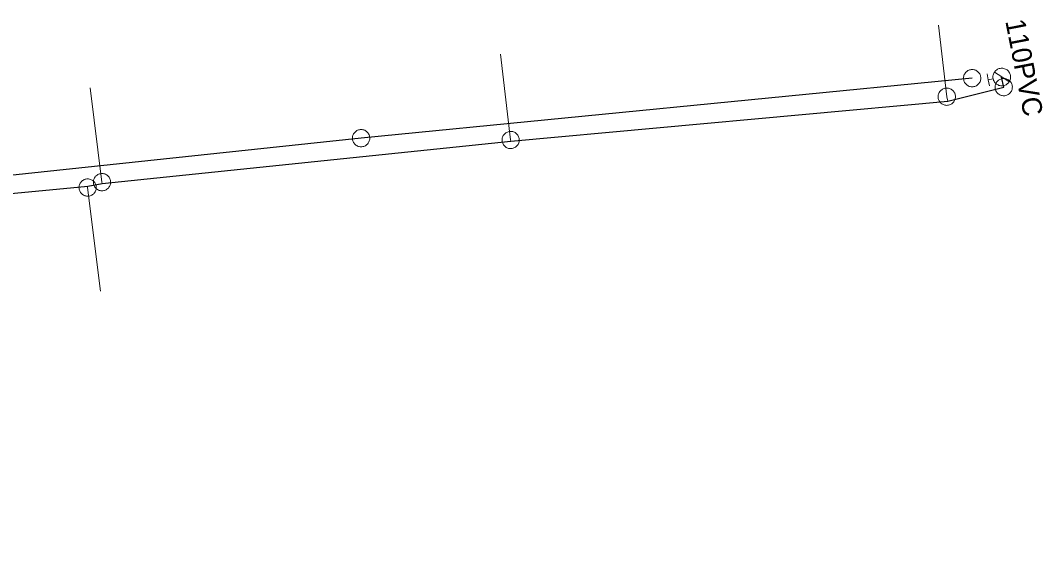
# Model space of a CAD drawing. Extents: x -741806 to -738704, y -1059275 to -1055387.
# Drawn here: x -740331.3 to -740279.6, y -1057572.5 to -1057546.2 of the extents above; entities that cross this region are included whole.
import ezdxf

# ---------------------------------------------------------------- set-up
doc = ezdxf.new("R2010")
doc.units = 0
doc.header["$LTSCALE"] = 0.4
for name, color, linetype, lineweight in [('2', 7, 'Continuous', 25), ('21', 7, 'Continuous', 13), ('3', 7, 'Continuous', 13), ('50', 7, 'Continuous', 13), ('51', 7, 'Continuous', 13), ('52', 7, 'Continuous', 25)]:
    doc.layers.add(name, color=color, linetype=linetype, lineweight=lineweight)
doc.layers.add('53', color=7, linetype='Continuous')

msp = doc.modelspace()

# ---------------------------------------------------------------- linework, layer by layer
at = {"layer": '2'}
msp.add_lwpolyline([(-740283.166, -1057549.12), (-740314.092, -1057552.159), (-740363.478, -1057557.404), (-740409.581, -1057562.408), (-740464.129, -1057568.401), (-740509.967, -1057572.304)], dxfattribs=at)
at = {"layer": '21'}
for points in [[(-740284.403, -1057550.291), (-740284.452, -1057550.058), (-740284.875, -1057546.442)], [(-740306.52, -1057552.313), (-740306.524, -1057552.25), (-740307.032, -1057547.902)], [(-740327.193, -1057554.446), (-740327.206, -1057554.386), (-740327.807, -1057549.607)], [(-740327.93, -1057554.585), (-740327.931, -1057554.659), (-740327.281, -1057559.914)]]:
    msp.add_lwpolyline(points, dxfattribs=at)
at = {"layer": '3'}
for points in [[(-740283.601, -1057549.162), (-740283.594, -1057549.206), (-740283.583, -1057549.25), (-740283.566, -1057549.294), (-740283.546, -1057549.334), (-740283.521, -1057549.373), (-740283.493, -1057549.409), (-740283.46, -1057549.441), (-740283.425, -1057549.471), (-740283.387, -1057549.495), (-740283.347, -1057549.517), (-740283.304, -1057549.533), (-740283.259, -1057549.546), (-740283.214, -1057549.553), (-740283.169, -1057549.556), (-740283.123, -1057549.554), (-740283.077, -1057549.547), (-740283.033, -1057549.535), (-740282.991, -1057549.52), (-740282.949, -1057549.499), (-740282.911, -1057549.474), (-740282.875, -1057549.445), (-740282.843, -1057549.414), (-740282.814, -1057549.378), (-740282.788, -1057549.34), (-740282.767, -1057549.299), (-740282.751, -1057549.256), (-740282.738, -1057549.213), (-740282.731, -1057549.167), (-740282.728, -1057549.121), (-740282.731, -1057549.075), (-740282.737, -1057549.031), (-740282.749, -1057548.987), (-740282.765, -1057548.943), (-740282.786, -1057548.902), (-740282.81, -1057548.864), (-740282.838, -1057548.828), (-740282.871, -1057548.796), (-740282.907, -1057548.766), (-740282.944, -1057548.742), (-740282.985, -1057548.72), (-740283.028, -1057548.704), (-740283.072, -1057548.691), (-740283.117, -1057548.683), (-740283.162, -1057548.681), (-740283.208, -1057548.683), (-740283.254, -1057548.69), (-740283.298, -1057548.701), (-740283.341, -1057548.717), (-740283.382, -1057548.738), (-740283.421, -1057548.763), (-740283.456, -1057548.792), (-740283.489, -1057548.823), (-740283.518, -1057548.859), (-740283.543, -1057548.897), (-740283.564, -1057548.938), (-740283.581, -1057548.981), (-740283.593, -1057549.024), (-740283.6, -1057549.07), (-740283.603, -1057549.116), (-740283.602, -1057549.161)], [(-740314.527, -1057552.201), (-740314.52, -1057552.245), (-740314.509, -1057552.289), (-740314.492, -1057552.333), (-740314.472, -1057552.373), (-740314.447, -1057552.412), (-740314.419, -1057552.448), (-740314.386, -1057552.48), (-740314.351, -1057552.51), (-740314.313, -1057552.534), (-740314.273, -1057552.556), (-740314.23, -1057552.572), (-740314.185, -1057552.585), (-740314.14, -1057552.592), (-740314.095, -1057552.595), (-740314.049, -1057552.593), (-740314.003, -1057552.586), (-740313.959, -1057552.574), (-740313.917, -1057552.559), (-740313.875, -1057552.538), (-740313.837, -1057552.513), (-740313.801, -1057552.484), (-740313.769, -1057552.453), (-740313.74, -1057552.417), (-740313.714, -1057552.379), (-740313.693, -1057552.338), (-740313.677, -1057552.295), (-740313.664, -1057552.252), (-740313.657, -1057552.206), (-740313.654, -1057552.16), (-740313.657, -1057552.114), (-740313.663, -1057552.07), (-740313.675, -1057552.026), (-740313.691, -1057551.982), (-740313.712, -1057551.941), (-740313.736, -1057551.903), (-740313.764, -1057551.867), (-740313.797, -1057551.835), (-740313.833, -1057551.805), (-740313.87, -1057551.781), (-740313.911, -1057551.759), (-740313.954, -1057551.743), (-740313.998, -1057551.73), (-740314.043, -1057551.722), (-740314.088, -1057551.72), (-740314.134, -1057551.722), (-740314.18, -1057551.729), (-740314.224, -1057551.74), (-740314.267, -1057551.756), (-740314.308, -1057551.777), (-740314.347, -1057551.802), (-740314.382, -1057551.831), (-740314.415, -1057551.862), (-740314.444, -1057551.898), (-740314.469, -1057551.936), (-740314.49, -1057551.977), (-740314.507, -1057552.02), (-740314.519, -1057552.063), (-740314.526, -1057552.109), (-740314.529, -1057552.155), (-740314.528, -1057552.2)]]:
    msp.add_lwpolyline(points, dxfattribs=at)
at = {"layer": '50'}
for p, q in [((-740282.413, -1057548.897), (-740282.352, -1057549.198)), ((-740281.668, -1057549.059), (-740282.036, -1057548.811)), ((-740282.106, -1057549.148), (-740282.352, -1057549.198)), ((-740282.291, -1057549.499), (-740282.352, -1057549.198)), ((-740281.668, -1057549.059), (-740281.295, -1057549.307))]:
    msp.add_line(p, q, dxfattribs=at)
msp.add_lwpolyline([(-740281.752, -1057548.623), (-740281.799, -1057548.635), (-740281.843, -1057548.649), (-740281.886, -1057548.671), (-740281.925, -1057548.696), (-740281.96, -1057548.723), (-740281.995, -1057548.757), (-740282.024, -1057548.793), (-740282.051, -1057548.832), (-740282.074, -1057548.872), (-740282.09, -1057548.916), (-740282.103, -1057548.961), (-740282.113, -1057549.007), (-740282.114, -1057549.054), (-740282.113, -1057549.1), (-740282.106, -1057549.146), (-740282.094, -1057549.19), (-740282.081, -1057549.234), (-740282.059, -1057549.276), (-740282.033, -1057549.316), (-740282.004, -1057549.354), (-740281.972, -1057549.386), (-740281.937, -1057549.417), (-740281.898, -1057549.443), (-740281.858, -1057549.464), (-740281.813, -1057549.483), (-740281.769, -1057549.496), (-740281.723, -1057549.503), (-740281.675, -1057549.508), (-740281.629, -1057549.504), (-740281.583, -1057549.501), (-740281.537, -1057549.488), (-740281.493, -1057549.471), (-740281.453, -1057549.452), (-740281.411, -1057549.427), (-740281.375, -1057549.397), (-740281.341, -1057549.366), (-740281.313, -1057549.33), (-740281.285, -1057549.291), (-740281.263, -1057549.248), (-740281.247, -1057549.206), (-740281.234, -1057549.16), (-740281.226, -1057549.114), (-740281.221, -1057549.07), (-740281.223, -1057549.02), (-740281.229, -1057548.974), (-740281.241, -1057548.93), (-740281.258, -1057548.886), (-740281.278, -1057548.843), (-740281.302, -1057548.804), (-740281.332, -1057548.766), (-740281.363, -1057548.734), (-740281.4, -1057548.703), (-740281.438, -1057548.678), (-740281.478, -1057548.655), (-740281.523, -1057548.64), (-740281.567, -1057548.624), (-740281.613, -1057548.616), (-740281.66, -1057548.615), (-740281.706, -1057548.616)], close=True, dxfattribs=at)
at = {"layer": '51'}
for points in [[(-740281.146, -1057549.463), (-740281.159, -1057549.42), (-740281.177, -1057549.378), (-740281.2, -1057549.338), (-740281.225, -1057549.301), (-740281.256, -1057549.266), (-740281.29, -1057549.235), (-740281.326, -1057549.208), (-740281.366, -1057549.184), (-740281.407, -1057549.166), (-740281.45, -1057549.151), (-740281.495, -1057549.14), (-740281.541, -1057549.135), (-740281.587, -1057549.134), (-740281.632, -1057549.138), (-740281.677, -1057549.147), (-740281.721, -1057549.161), (-740281.763, -1057549.179), (-740281.803, -1057549.201), (-740281.84, -1057549.228), (-740281.875, -1057549.259), (-740281.906, -1057549.292), (-740281.933, -1057549.328), (-740281.956, -1057549.368), (-740281.976, -1057549.409), (-740281.99, -1057549.453), (-740282.001, -1057549.498), (-740282.006, -1057549.543), (-740282.006, -1057549.589), (-740282.002, -1057549.635), (-740281.994, -1057549.68), (-740281.98, -1057549.723), (-740281.962, -1057549.765), (-740281.939, -1057549.805), (-740281.913, -1057549.842), (-740281.883, -1057549.877), (-740281.849, -1057549.908), (-740281.812, -1057549.935), (-740281.773, -1057549.959), (-740281.731, -1057549.977), (-740281.688, -1057549.992), (-740281.643, -1057550.003), (-740281.597, -1057550.008), (-740281.552, -1057550.008), (-740281.506, -1057550.005), (-740281.461, -1057549.995), (-740281.417, -1057549.982), (-740281.376, -1057549.963), (-740281.336, -1057549.942), (-740281.298, -1057549.915), (-740281.264, -1057549.884), (-740281.233, -1057549.851), (-740281.205, -1057549.815), (-740281.182, -1057549.775), (-740281.163, -1057549.734), (-740281.148, -1057549.69), (-740281.138, -1057549.645), (-740281.133, -1057549.6), (-740281.132, -1057549.554), (-740281.136, -1057549.508), (-740281.146, -1057549.464)], [(-740284.541, -1057549.63), (-740284.584, -1057549.641), (-740284.627, -1057549.657), (-740284.668, -1057549.678), (-740284.706, -1057549.702), (-740284.742, -1057549.731), (-740284.775, -1057549.764), (-740284.803, -1057549.799), (-740284.829, -1057549.837), (-740284.849, -1057549.878), (-740284.866, -1057549.921), (-740284.878, -1057549.965), (-740284.886, -1057550.011), (-740284.889, -1057550.056), (-740284.886, -1057550.102), (-740284.879, -1057550.147), (-740284.867, -1057550.192), (-740284.851, -1057550.234), (-740284.831, -1057550.275), (-740284.805, -1057550.313), (-740284.776, -1057550.349), (-740284.744, -1057550.381), (-740284.709, -1057550.411), (-740284.67, -1057550.435), (-740284.63, -1057550.457), (-740284.587, -1057550.473), (-740284.542, -1057550.485), (-740284.498, -1057550.492), (-740284.451, -1057550.495), (-740284.406, -1057550.492), (-740284.36, -1057550.486), (-740284.317, -1057550.474), (-740284.274, -1057550.458), (-740284.233, -1057550.437), (-740284.195, -1057550.412), (-740284.159, -1057550.383), (-740284.126, -1057550.351), (-740284.098, -1057550.315), (-740284.072, -1057550.277), (-740284.052, -1057550.236), (-740284.035, -1057550.194), (-740284.023, -1057550.15), (-740284.015, -1057550.104), (-740284.013, -1057550.059), (-740284.015, -1057550.013), (-740284.022, -1057549.968), (-740284.034, -1057549.923), (-740284.051, -1057549.881), (-740284.071, -1057549.84), (-740284.096, -1057549.801), (-740284.125, -1057549.765), (-740284.157, -1057549.733), (-740284.192, -1057549.704), (-740284.231, -1057549.679), (-740284.271, -1057549.658), (-740284.314, -1057549.642), (-740284.359, -1057549.629), (-740284.403, -1057549.622), (-740284.45, -1057549.62), (-740284.495, -1057549.622), (-740284.54, -1057549.629)], [(-740306.558, -1057551.814), (-740306.602, -1057551.819), (-740306.647, -1057551.83), (-740306.69, -1057551.845), (-740306.731, -1057551.865), (-740306.77, -1057551.889), (-740306.807, -1057551.917), (-740306.84, -1057551.949), (-740306.87, -1057551.983), (-740306.895, -1057552.021), (-740306.917, -1057552.061), (-740306.935, -1057552.104), (-740306.948, -1057552.148), (-740306.957, -1057552.193), (-740306.96, -1057552.238), (-740306.959, -1057552.284), (-740306.953, -1057552.33), (-740306.942, -1057552.374), (-740306.927, -1057552.417), (-740306.907, -1057552.458), (-740306.882, -1057552.498), (-740306.855, -1057552.534), (-740306.824, -1057552.567), (-740306.788, -1057552.597), (-740306.751, -1057552.623), (-740306.71, -1057552.645), (-740306.668, -1057552.662), (-740306.625, -1057552.675), (-740306.579, -1057552.683), (-740306.533, -1057552.687), (-740306.487, -1057552.686), (-740306.443, -1057552.679), (-740306.398, -1057552.669), (-740306.355, -1057552.653), (-740306.314, -1057552.634), (-740306.275, -1057552.61), (-740306.238, -1057552.582), (-740306.205, -1057552.55), (-740306.175, -1057552.516), (-740306.15, -1057552.478), (-740306.128, -1057552.438), (-740306.11, -1057552.395), (-740306.097, -1057552.351), (-740306.089, -1057552.306), (-740306.085, -1057552.261), (-740306.086, -1057552.215), (-740306.092, -1057552.169), (-740306.104, -1057552.125), (-740306.118, -1057552.082), (-740306.138, -1057552.04), (-740306.163, -1057552.001), (-740306.19, -1057551.965), (-740306.221, -1057551.932), (-740306.257, -1057551.902), (-740306.294, -1057551.876), (-740306.335, -1057551.854), (-740306.377, -1057551.837), (-740306.42, -1057551.824), (-740306.466, -1057551.816), (-740306.512, -1057551.812), (-740306.557, -1057551.814)], [(-740327.291, -1057553.957), (-740327.334, -1057553.968), (-740327.377, -1057553.983), (-740327.419, -1057554.004), (-740327.457, -1057554.028), (-740327.493, -1057554.057), (-740327.526, -1057554.089), (-740327.555, -1057554.124), (-740327.581, -1057554.162), (-740327.602, -1057554.203), (-740327.619, -1057554.245), (-740327.631, -1057554.289), (-740327.639, -1057554.335), (-740327.643, -1057554.38), (-740327.641, -1057554.426), (-740327.634, -1057554.471), (-740327.623, -1057554.516), (-740327.607, -1057554.559), (-740327.586, -1057554.599), (-740327.561, -1057554.638), (-740327.533, -1057554.674), (-740327.501, -1057554.707), (-740327.466, -1057554.736), (-740327.428, -1057554.761), (-740327.388, -1057554.783), (-740327.344, -1057554.8), (-740327.3, -1057554.812), (-740327.256, -1057554.82), (-740327.209, -1057554.823), (-740327.164, -1057554.821), (-740327.118, -1057554.815), (-740327.075, -1057554.803), (-740327.032, -1057554.787), (-740326.99, -1057554.767), (-740326.952, -1057554.743), (-740326.916, -1057554.714), (-740326.883, -1057554.682), (-740326.854, -1057554.647), (-740326.828, -1057554.609), (-740326.807, -1057554.568), (-740326.79, -1057554.526), (-740326.778, -1057554.481), (-740326.77, -1057554.436), (-740326.767, -1057554.391), (-740326.768, -1057554.345), (-740326.776, -1057554.3), (-740326.786, -1057554.255), (-740326.803, -1057554.212), (-740326.823, -1057554.171), (-740326.848, -1057554.132), (-740326.876, -1057554.096), (-740326.908, -1057554.064), (-740326.943, -1057554.034), (-740326.981, -1057554.009), (-740327.021, -1057553.988), (-740327.065, -1057553.971), (-740327.109, -1057553.958), (-740327.153, -1057553.951), (-740327.2, -1057553.948), (-740327.245, -1057553.95), (-740327.29, -1057553.957)], [(-740327.937, -1057555.095), (-740327.892, -1057555.094), (-740327.847, -1057555.088), (-740327.802, -1057555.076), (-740327.759, -1057555.061), (-740327.718, -1057555.04), (-740327.679, -1057555.016), (-740327.643, -1057554.987), (-740327.61, -1057554.956), (-740327.582, -1057554.92), (-740327.556, -1057554.883), (-740327.534, -1057554.842), (-740327.517, -1057554.799), (-740327.504, -1057554.755), (-740327.497, -1057554.71), (-740327.494, -1057554.664), (-740327.495, -1057554.618), (-740327.502, -1057554.573), (-740327.513, -1057554.529), (-740327.53, -1057554.486), (-740327.55, -1057554.445), (-740327.575, -1057554.406), (-740327.602, -1057554.37), (-740327.635, -1057554.337), (-740327.669, -1057554.308), (-740327.708, -1057554.282), (-740327.749, -1057554.261), (-740327.79, -1057554.244), (-740327.835, -1057554.232), (-740327.88, -1057554.224), (-740327.926, -1057554.221), (-740327.971, -1057554.223), (-740328.016, -1057554.229), (-740328.061, -1057554.241), (-740328.104, -1057554.256), (-740328.145, -1057554.277), (-740328.184, -1057554.301), (-740328.22, -1057554.33), (-740328.253, -1057554.361), (-740328.281, -1057554.397), (-740328.307, -1057554.434), (-740328.329, -1057554.475), (-740328.346, -1057554.518), (-740328.358, -1057554.562), (-740328.366, -1057554.607), (-740328.369, -1057554.653), (-740328.368, -1057554.699), (-740328.36, -1057554.744), (-740328.35, -1057554.788), (-740328.333, -1057554.831), (-740328.313, -1057554.872), (-740328.288, -1057554.911), (-740328.261, -1057554.947), (-740328.228, -1057554.98), (-740328.194, -1057555.009), (-740328.155, -1057555.034), (-740328.114, -1057555.056), (-740328.073, -1057555.073), (-740328.028, -1057555.085), (-740327.983, -1057555.093), (-740327.938, -1057555.095)]]:
    msp.add_lwpolyline(points, dxfattribs=at)
at = {"layer": '52'}
msp.add_line((-740281.57, -1057549.571), (-740281.673, -1057549.06), dxfattribs=at)
msp.add_lwpolyline([(-740501.975, -1057565.431), (-740498.884, -1057570.244), (-740497.519, -1057572.537), (-740481.265, -1057571.105), (-740444.131, -1057566.855), (-740420.085, -1057564.335), (-740405.726, -1057562.816), (-740391.932, -1057561.267), (-740379.41, -1057560.259), (-740347.938, -1057556.495), (-740327.93, -1057554.585), (-740327.193, -1057554.446), (-740306.52, -1057552.313), (-740284.403, -1057550.291), (-740281.57, -1057549.571)], dxfattribs=at)

# ---------------------------------------------------------------- texts
at = {"layer": '53'}
msp.add_text('110PVC', height=1, rotation=281, dxfattribs=at).set_placement((-740281.492, -1057546.228))

doc.saveas('drawing.dxf')
